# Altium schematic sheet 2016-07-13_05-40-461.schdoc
size 309 x 144 mm; SheetNumber: 1; SheetTotal: 1
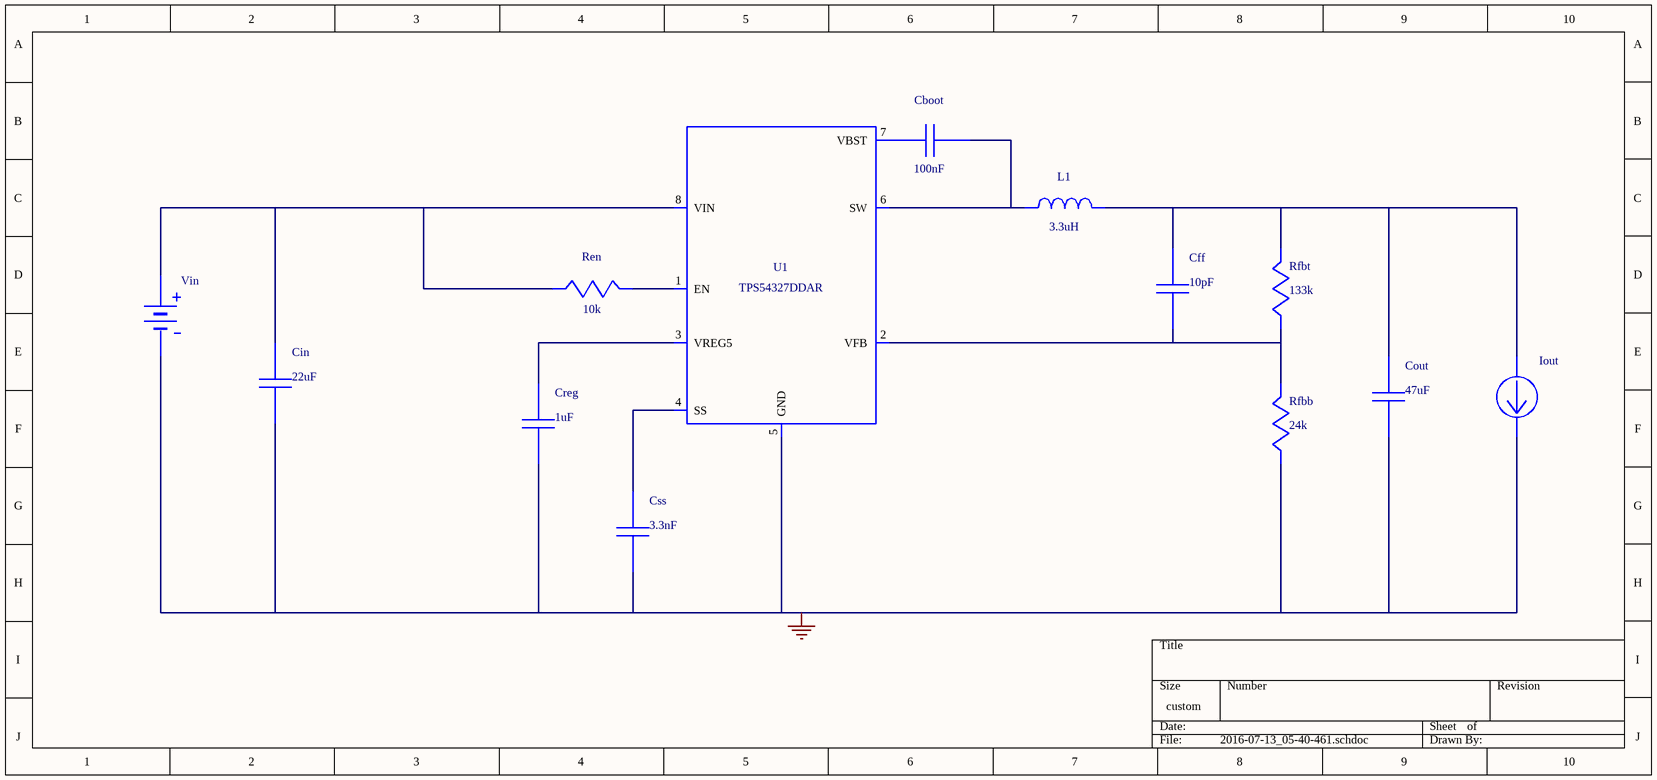
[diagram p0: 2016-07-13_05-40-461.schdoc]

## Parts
Cboot  value 100nF  (hidden comment: GRM155R61A104KA01D)
Cff  value 10pF  (hidden comment: C0805C100M4GACTU)
Cin  value 22uF  (hidden comment: GRM32ER61E226KE15L)
Cout  value 47uF  (hidden comment: C3216JB1A476M)
Creg  value 1uF  (hidden comment: GRM188R61A105KA61D)
Css  value 3.3nF  (hidden comment: GRM216R71E332KA01D)
Iout  WB_CURRENT_LOAD  (value not drawn)
L1  value 3.3uH  (hidden comment: SRN6045-3R3Y)
Ren  value 10k  (hidden comment: CRCW040210K0FKED)
Rfbb  value 24k  (hidden comment: RC0603FR-0724KL)
Rfbt  value 133k  (hidden comment: CRCW0402133KFKED)
U1  TPS54327DDAR
Vin  WB_BATTERY  (value not drawn)

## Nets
0: Cin.2 Cout.2 Creg.2 Css.2 Iout.2(-) Rfbb.2 U1.5(GND) U1.9(ETPAD) Vin.2(-)
NetCboot_1: Cboot.1 U1.7(VBST)
NetCboot_2: Cboot.2 L1.2 U1.6(SW)
NetCff_1: Cff.1 Cout.1 Iout.1(+) L1.1 Rfbt.1
NetCff_2: Cff.2 Rfbb.1 Rfbt.2 U1.2(VFB)
NetCin_1: Cin.1 Ren.2 U1.8(VIN) Vin.1(+)
NetCreg_1: Creg.1 U1.3(VREG5)
NetCss_1: Css.1 U1.4(SS)
NetRen_1: Ren.1 U1.1(EN)

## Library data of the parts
Cboot = GRM155R61A104KA01D: GRM155R61A104KA0; Manufacturer Name: MuRata
Cff = C0805C100M4GACTU: Manufacturer Name: Kemet
Cin = GRM32ER61E226KE15L: GRM32ER61E226KE1; Manufacturer Name: MuRata
Cout = C3216JB1A476M: Manufacturer Name: TDK
Creg = GRM188R61A105KA61D: GRM188R61A105KA6; Manufacturer Name: MuRata
Css = GRM216R71E332KA01D: GRM216R71E332KA0; Manufacturer Name: MuRata
L1 = SRN6045-3R3Y: Manufacturer Name: Bourns
Ren = CRCW040210K0FKED: Manufacturer Name: Vishay-Dale
Rfbb = RC0603FR-0724KL: Manufacturer Name: Yageo America
Rfbt = CRCW0402133KFKED: Manufacturer Name: Vishay-Dale
U1 = TPS54327DDAR: Manufacturer Name: Texas Instruments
